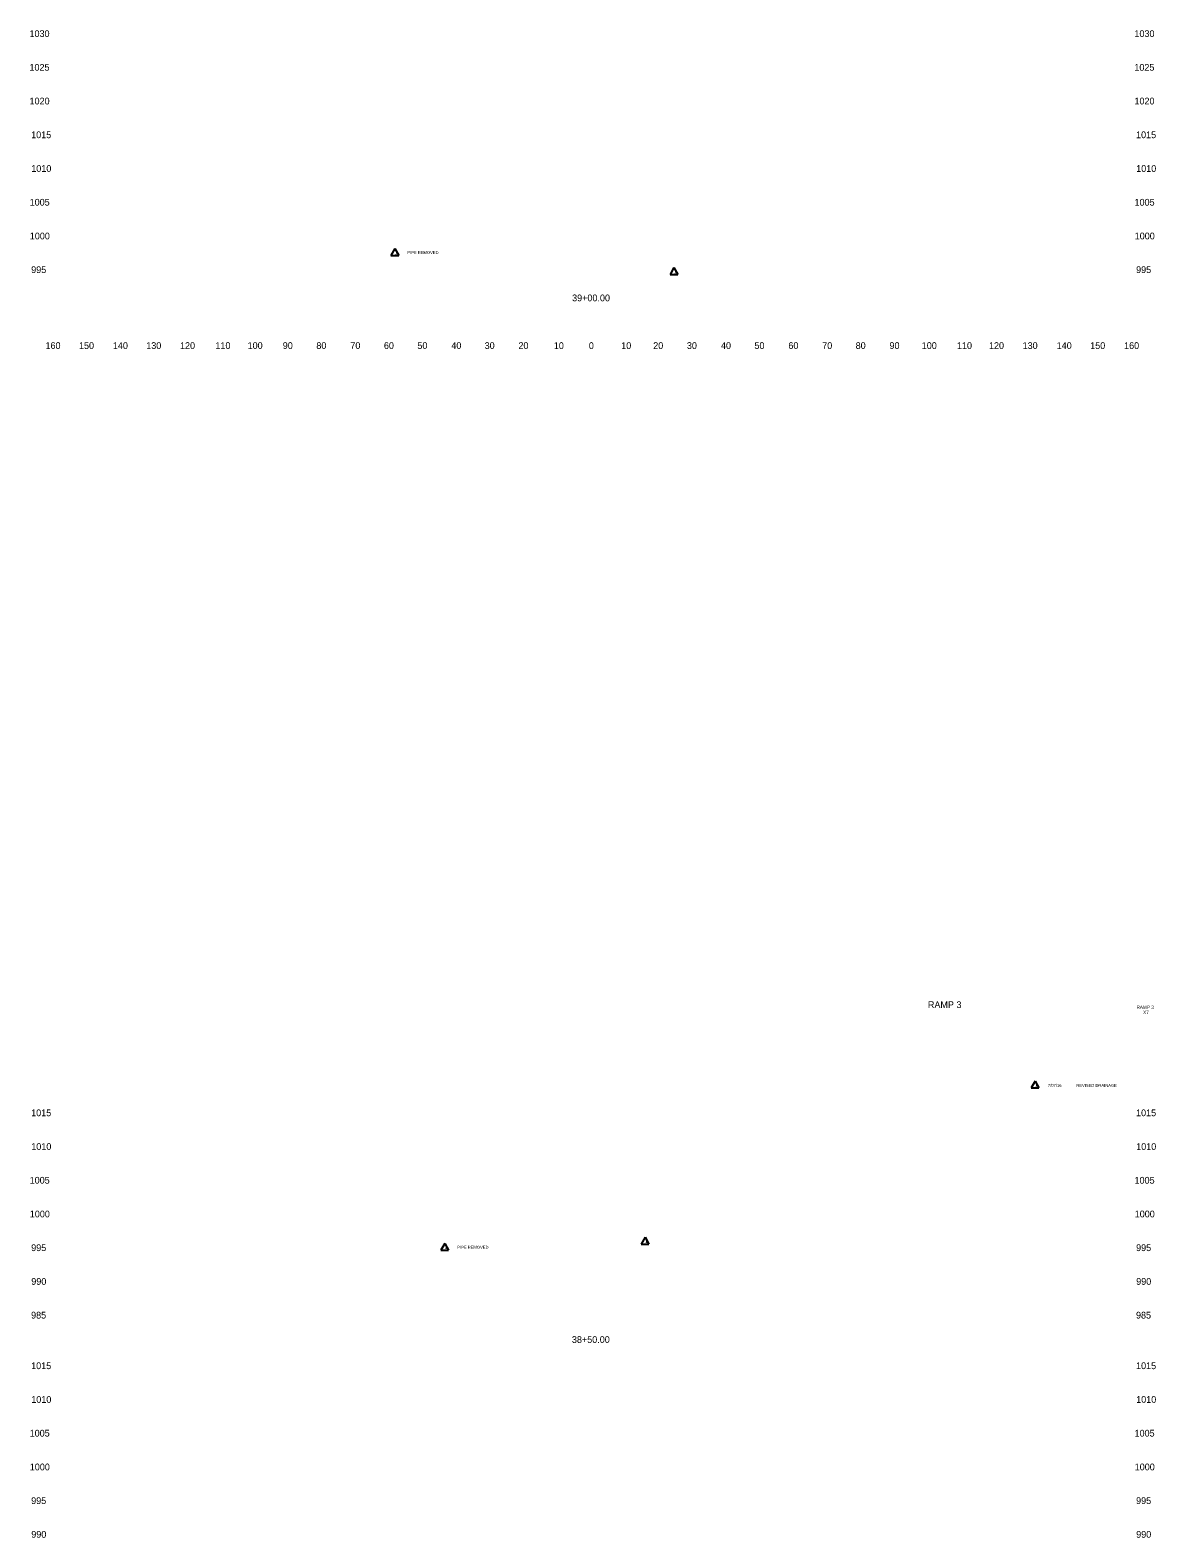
# Model space of a CAD drawing. Extents: x 4994 to 5843, y 4997 to 8804.
# Drawn here: x 4993.5 to 5327.5, y 7445 to 7892 of the extents above; entities that cross this region are included whole.
import ezdxf

# ---------------------------------------------------------------- set-up
doc = ezdxf.new("R2010")
doc.units = 0
for name, color, linetype in [('RD_SHT_ID', 7, 'Continuous'), ('RD_SHT_TX', 7, 'Continuous'), ('RD_XS_TX_Offset', 7, 'Continuous'), ('RD_XS_TX_Station', 7, 'Continuous')]:
    doc.layers.add(name, color=color, linetype=linetype)

msp = doc.modelspace()

# ---------------------------------------------------------------- linework, layer by layer
at = {"layer": 'RD_SHT_TX'}
for p, q in [((5101.74, 7827.24), (5100.6, 7825.21)), ((5100.6, 7825.21), (5102.88, 7825.21)), ((5101.74, 7827.24), (5102.88, 7825.21)), ((5184.53, 7821.61), (5183.39, 7819.58)), ((5183.39, 7819.58), (5185.66, 7819.58)), ((5184.53, 7821.61), (5185.66, 7819.58)), ((5291.7, 7580.43), (5290.56, 7578.4)), ((5290.56, 7578.4), (5292.84, 7578.4)), ((5291.7, 7580.43), (5292.84, 7578.4)), ((5176, 7534.11), (5174.86, 7532.08)), ((5176, 7534.11), (5177.14, 7532.08)), ((5116.56, 7532.29), (5115.42, 7530.26)), ((5115.42, 7530.26), (5117.7, 7530.26)), ((5116.56, 7532.29), (5117.7, 7530.26)), ((5174.86, 7532.08), (5177.14, 7532.08))]:
    msp.add_line(p, q, dxfattribs=at)

# ---------------------------------------------------------------- texts
at = {"layer": 'RD_SHT_ID'}
for s, height, p in [('RAMP 3', 2, (5259.89, 7602.06)), ('RAMP 3', 1, (5321.78, 7601.8)), ('X7', 1, (5323.74, 7600.3))]:
    msp.add_text(s, height=height, dxfattribs=at).set_placement(p)
at = {"layer": 'RD_SHT_TX'}
for s, p in [('1', (5101.74, 7825.54)), ('PIPE REMOVED', (5105.45, 7825.63)), ('1', (5184.53, 7819.91)), ('1', (5291.7, 7578.72)), ('7/07/16', (5295.48, 7578.69)), ('REVISED DRAINAGE', (5303.93, 7578.69)), ('1', (5176, 7532.41)), ('1', (5116.56, 7530.59)), ('PIPE REMOVED', (5120.28, 7530.68))]:
    msp.add_text(s, height=0.88, dxfattribs=at).set_placement(p)
at = {"layer": 'RD_XS_TX_Offset'}
for s, p in [('1030', (4993.36, 7890)), ('1030', (5321.16, 7890)), ('1025', (4993.34, 7880)), ('1025', (5321.14, 7880)), ('1020', (4993.37, 7870)), ('1020', (5321.17, 7870)), ('1015', (4993.85, 7860)), ('1015', (5321.65, 7860)), ('1010', (4993.88, 7850)), ('1010', (5321.68, 7850)), ('1005', (4993.4, 7840)), ('1005', (5321.2, 7840)), ('1000', (4993.44, 7830)), ('1000', (5321.24, 7830)), ('995', (4993.86, 7820)), ('995', (5321.66, 7820)), ('160', (4998.1, 7797.5)), ('150', (5008.04, 7797.5)), ('140', (5018.1, 7797.5)), ('130', (5027.99, 7797.5)), ('120', (5038.01, 7797.5)), ('110', (5048.51, 7797.5)), ('100', (5058.07, 7797.5)), ('90', (5068.5, 7797.5)), ('80', (5078.46, 7797.5)), ('70', (5088.54, 7797.5)), ('60', (5098.5, 7797.5)), ('50', (5108.43, 7797.5)), ('40', (5118.5, 7797.5)), ('30', (5128.39, 7797.5)), ('20', (5138.4, 7797.5)), ('10', (5148.91, 7797.5)), ('0', (5159.3, 7797.5)), ('0', (5159.3, 7797.5)), ('10', (5168.91, 7797.5)), ('20', (5178.4, 7797.5)), ('30', (5188.39, 7797.5)), ('40', (5198.5, 7797.5)), ('50', (5208.43, 7797.5)), ('60', (5218.5, 7797.5)), ('70', (5228.54, 7797.5)), ('80', (5238.46, 7797.5)), ('90', (5248.5, 7797.5)), ('100', (5258.07, 7797.5)), ('110', (5268.51, 7797.5)), ('120', (5278.01, 7797.5)), ('130', (5287.99, 7797.5)), ('140', (5298.1, 7797.5)), ('150', (5308.04, 7797.5)), ('160', (5318.1, 7797.5)), ('1015', (4993.85, 7570)), ('1015', (5321.65, 7570)), ('1010', (4993.88, 7560)), ('1010', (5321.68, 7560)), ('1005', (4993.4, 7550)), ('1005', (5321.2, 7550)), ('1000', (4993.44, 7540)), ('1000', (5321.24, 7540)), ('995', (4993.86, 7530)), ('995', (5321.66, 7530)), ('990', (4993.89, 7520)), ('990', (5321.69, 7520)), ('985', (4993.83, 7510)), ('985', (5321.63, 7510)), ('1015', (4993.85, 7495)), ('1015', (5321.65, 7495)), ('1010', (4993.88, 7485)), ('1010', (5321.68, 7485)), ('1005', (4993.4, 7475)), ('1005', (5321.2, 7475)), ('1000', (4993.44, 7465)), ('1000', (5321.24, 7465)), ('995', (4993.86, 7455)), ('995', (5321.66, 7455)), ('990', (4993.89, 7445)), ('990', (5321.69, 7445))]:
    msp.add_text(s, height=2, dxfattribs=at).set_placement(p)
at = {"layer": 'RD_XS_TX_Station'}
for s, p in [('39+00.00', (5154.34, 7811.64)), ('38+50.00', (5154.28, 7502.77))]:
    msp.add_text(s, height=2, dxfattribs=at).set_placement(p)

doc.saveas('drawing.dxf')
